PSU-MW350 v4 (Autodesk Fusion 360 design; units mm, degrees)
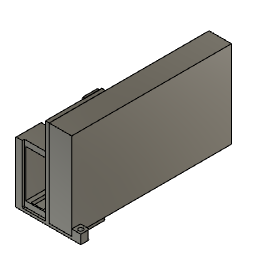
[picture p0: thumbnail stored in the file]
sketch "Sketch1" plane through (0, 0, 0) normal (0, 1, 0) x axis (1, 0, 0)
  line L1 (-34.05, -7.3872) -> (-6.55, -7.3872)
  line L2 (-34.05, -69.3872) -> (-34.05, -7.3872)
  line L3 (-6.55, -69.3872) -> (-34.05, -69.3872)
  line L4 (-6.55, -7.3872) -> (-6.55, -69.3872)
  line L5 (29.5, 0) -> (0, 0)
  line L6 (29.5, -114.5) -> (29.5, 0)
  line L7 (0, -114.5) -> (29.5, -114.5)
  line L8 (0, 0) -> (0, -114.5)
  line L9 (-35.5, -0.1) -> (-5.1, -0.1)
  line L10 (-35.5, -76.6744) -> (-35.5, -0.1)
  line L11 (-5.1, -76.6744) -> (-35.5, -76.6744)
  line L12 (-5.1, -0.1) -> (-5.1, -76.6744)
  line L13 (-5.1, -0.1) -> (-35.5, -76.6744)
  line L14 (-6.55, -69.3872) -> (-34.05, -7.3872)
  line L15 (-44.5, 0) -> (0, 0)
  line L16 (-44.5, -76.7744) -> (-44.5, 0)
  line L17 (-5, -76.7744) -> (-44.5, -76.7744)
  line L18 (-5, -114.5) -> (-5, -76.7744)
  line L19 (0, -114.5) -> (-5, -114.5)
  line L20 (-35.6, 0) -> (-35.6, -76.7744)
  line L21 (-28.3, -2.9315) -> (-28.3, -7.3872)
  line L22 (-12.3, -2.9315) -> (-28.3, -2.9315)
  line L23 (-12.3, -7.3872) -> (-12.3, -2.9315)
  line L24 (-28.3, -73.8428) -> (-28.3, -69.3872)
  line L25 (-12.3, -73.8428) -> (-28.3, -73.8428)
  line L26 (-12.3, -69.3872) -> (-12.3, -73.8428)
  line L27 (-5, 0) -> (-5, -76.7744)
  line L28 (41.5, -8.53) -> (29.5, -8.53)
  line L29 (41.5, 3.47) -> (41.5, -8.53)
  line L30 (-44.5, 3.47) -> (41.5, 3.47)
  line L31 (-44.5, 0) -> (-44.5, 3.47)
  point P1 (0, 0)
  point P14 (-20.3, -38.3872)
  point P15 (-20.3, -38.3872)
  point P16 (0, 0)
  point P21 (0, -114.5)
  point P9 (0, -114.5)
  point P22 (-35.6, -76.7744)
  point P23 (-35.6, 0)
  point P24 (-28.3, -7.3872)
  point P27 (-12.3, -7.3872)
  point P28 (-28.3, -69.3872)
  point P31 (-12.3, -69.3872)
  point P32 (-5, 0)
  point P33 (29.5, -8.53)
  point P17 (-44.5, 0)
  point P37 (-44.5, 0)
  point P6 (0, 0)
  point P7 (29.5, 0)
  point P8 (29.5, -114.5)
  point P4 (-34.05, -69.3872)
  point P5 (-6.55, -69.3872)
  point P3 (-34.05, -7.3872)
  point P11 (-35.5, -0.1)
  point P12 (-35.5, -76.6744)
  point P13 (-5.1, -76.6744)
  point P25 (-28.3, -2.9315)
  point P19 (-5, -76.7744)
  point P34 (41.5, -8.53)
  point P35 (41.5, 3.47)
  horizontal L1
  vertical L2
  horizontal L3
  vertical L4
  horizontal L5
  vertical L6
  horizontal L7
  vertical L8
  coincident P1 L8
  coincident P1 L5
  horizontal L9
  vertical L10
  horizontal L11
  vertical L12
  midpoint L13 P14
  midpoint L14 P15
  coincident P14 P15
  coincident P1 P16
  perpendicular L8 L15
  perpendicular L15 L16
  perpendicular L16 L17
  perpendicular L17 L18
  coincident L8 P21
  perpendicular L8 L19
  coincident P9 P21
  coincident L17 P22
  perpendicular L17 L20
  coincident L15 P23
  coincident L1 P24
  perpendicular L1 L21
  perpendicular L21 L22
  coincident L1 P27
  perpendicular L1 L23
  coincident L3 P28
  perpendicular L3 L24
  perpendicular L24 L25
  coincident L3 P31
  perpendicular L3 L26
  coincident P24 L24
  coincident P27 L26
  equal L21 L24
  perpendicular L15 L27
  coincident L15 P32
  coincident L6 P33
  perpendicular L6 L28
  perpendicular L5 L29
  perpendicular L16 L30
  perpendicular L30 L31
  coincident P17 P37
  dimension "d1" distance P6 P7 = 29.5
  dimension "d2" distance P7 P8 = 114.5
  dimension "d3" distance P4 P5 = 27.5
  dimension "d4" distance P3 P4 = 62
  dimension "d6" distance P11 P12 = 76.5744
  dimension "d7" distance P12 P13 = 30.4
  dimension "d9" distance P1 L9 = 0.1
  dimension "d10" distance P9 L18 = 5
  dimension "d11" distance L11 L17 = 0.1
  dimension "d12" distance L10 L16 = 9
  dimension "d13" distance L10 L20 = 0.1
  dimension "d15" distance P24 P25 = 4.4557
  dimension "d16" distance P14 L24 = 8
  dimension "d17" distance P15 L26 = 8 (= "d16")
  dimension "d18" distance L12 P19 = 0.1
  dimension "d42" distance P33 P34 = 12
  dimension "d43" distance L5 L30 = 3.47
  dimension "d44" distance P34 P35 = 12
extrude "Extrude1" new body sketch "Sketch1" profile of L5 L6 L8 L15 L18 L19 L27 L28 L29 L30 L31 along normal blind 45
extrude "Extrude2" add sketch "Sketch1" profile of L1 L2 L3 L4 L15 L16 L17 L20 L21 L22 L23 L24 L25 L26 L27 along normal blind 33
extrude "Extrude3" cut sketch "Sketch1" profile of L1 L2 L3 L4 L15 L17 L20 L21 L22 L23 L24 L25 L26 L27 along normal blind 3
extrude "Extrude4" sketch "Sketch1" profile of L1 L3 L21 L22 L23 L24 L25 L26 blind 1.5
fillet "Fillet1" radius 1
fillet "Fillet2" radius 3
fillet "Fillet3" radius 1
fillet "Fillet4" radius 1
extrude "Extrude5" new body sketch "Sketch1" profile of L5 L6 L7 L8 along normal blind 210.25 (= "150 mm + 60.25 mm") bodies "PSU"
sketch "Sketch2" plane through (0, 0, 0) normal (-1, 0, 0) x axis (0, -1, 0)
  line L1 (0, 114.5) -> (0, 0)
  line L2 (-210.25, 114.5) -> (0, 114.5)
  line L3 (-210.25, 0) -> (-210.25, 114.5)
  line L4 (0, 0) -> (-210.25, 0)
  line L5 (-180.125, 32.25) -> (-30.125, 32.25)
  line L6 (-180.125, 82.25) -> (-180.125, 32.25)
  line L7 (-30.125, 82.25) -> (-180.125, 82.25)
  line L8 (-30.125, 32.25) -> (-30.125, 82.25)
  line L9 (0, 114.5) -> (-210.25, 0)
  line L10 (-30.125, 32.25) -> (-180.125, 82.25)
  circle C1 centre (-180.125, 82.25) radius 2.25
  circle C2 centre (-180.125, 32.25) radius 2.25
  circle C3 centre (-30.125, 32.25) radius 2.25
  circle C4 centre (-30.125, 82.25) radius 2.25
  point P5 (-210.25, 0)
  point P10 (-210.25, 0)
  point P3 (0, 114.5)
  point P11 (0, 114.5)
  point P12 (-105.125, 57.25)
  point P13 (-105.125, 57.25)
  point P8 (-180.125, 82.25)
  point P14 (-180.125, 82.25)
  point P7 (-180.125, 32.25)
  point P15 (-180.125, 32.25)
  point P6 (-30.125, 32.25)
  point P16 (-30.125, 32.25)
  point P9 (-30.125, 82.25)
  point P17 (-30.125, 82.25)
  horizontal L5
  vertical L6
  horizontal L7
  vertical L8
  coincident P5 P10
  coincident P3 P11
  midpoint L9 P12
  midpoint L10 P13
  coincident P12 P13
  coincident P8 P14
  coincident P7 P15
  coincident P6 P16
  coincident P9 P17
  equal C3 C4
  equal C2 C4
  equal C1 C2
  dimension "d34" distance P6 P9 = 50
  dimension "d35" distance P8 P9 = 150
  dimension "d36" diameter C4 = 4.5
extrude "Extrude6" cut sketch "Sketch2" + "Sketch3" profile of S1:C4 blind 50
sketch "Sketch3" plane through (0, 0, 0) normal (0, 0, -1) x axis (1, 0, 0)
  line L1 (0, 0) -> (29.5, 0)
  line L2 (0, -210.25) -> (0, 0)
  line L3 (29.5, -210.25) -> (0, -210.25)
  line L4 (29.5, 0) -> (29.5, -210.25)
  line L5 (12.5, -30.125) -> (12.5, -180.125)
  circle C1 centre (12.5, -30.125) radius 2.125
  circle C2 centre (12.5, -180.125) radius 2.125
  point P7 (12.5, -180.125)
  point P8 (12.5, -180.125)
  point P6 (12.5, -30.125)
  point P9 (12.5, -30.125)
  point P10 (0, -30.125)
  point P11 (0, -180.125)
  coincident P7 P8
  vertical L5
  coincident P6 P9
  horizontal P6 P10
  horizontal P7 P11
  equal C1 C2
  dimension "d40" diameter C1 = 4.25
  dimension "d41" distance L2 L5 = 12.5
extrude "Extrude7" cut sketch "Sketch3" profile of C1 along normal blind 25
fillet "Fillet5" radius 1
sketch "Sketch4" plane through (0, 0, -3.47) normal (0, 0, -1) x axis (1, 0, 0)
  line L1 (-44.5, 0) -> (41.5, 0)
  line L2 (-44.5, -45) -> (-44.5, 0)
  line L3 (41.5, -45) -> (-44.5, -45)
  line L4 (41.5, 0) -> (41.5, -45)
  line L5 (41.5, -11.54) -> (29.5, -11.54)
  line L6 (-5, -33) -> (-5, -45)
  line L7 (-44.5, -33) -> (-5, -33)
  line L8 (29.5, -210.25) -> (29.5, 0)
  line L9 (-0.1, -186.125) -> (-0.1, -174.125)
  line L10 (18.5, -186.125) -> (-0.1, -186.125)
  line L11 (18.5, -174.125) -> (18.5, -186.125)
  line L12 (-0.1, -174.125) -> (18.5, -174.125)
  line L13 (-12.84, -174.125) -> (-0.1, -174.125)
  line L14 (-12.84, -186.125) -> (-12.84, -174.125)
  line L15 (-0.1, -186.125) -> (-12.84, -186.125)
  line L16 (0, -210.25) -> (0, 0)
  line L17 (-6.47, -180.125) -> (-12.84, -180.125)
  line L18 (-2.64, -186.125) -> (-2.64, -174.125)
  circle C1 centre (12.5, -30.125) radius 2.125
  circle C2 centre (-38.96, -5.54) radius 7.5
  circle C3 centre (-38.96, -5.54) radius 3
  circle C4 centre (35.96, -5.54) radius 3
  circle C5 centre (35.96, -5.54) radius 7.5
  circle C6 centre (-6.47, -180.125) radius 3
  circle C7 centre (-6.47, -180.125) radius 7.5
  circle C8 centre (12.5, -180.125) radius 2.125
  point P9 (-41.96, -5.54)
  point P7 (-38.96, -5.54)
  point P10 (-38.96, -2.54)
  point P8 (-38.96, -5.54)
  point P11 (35.96, -5.54)
  point P15 (38.96, -5.54)
  point P12 (35.96, -5.54)
  point P17 (41.5, -11.54)
  point P18 (-5, -45)
  point P16 (29.5, -11.54)
  point P20 (-44.5, -33)
  point P21 (-44.5, -33)
  point P24 (-5, -45)
  point P25 (12.5, -180.125)
  point P26 (12.5, -180.125)
  point P13 (-6.47, -180.125)
  point P27 (-0.1, -174.125)
  point P31 (-0.1, -174.125)
  point P28 (-0.1, -186.125)
  point P34 (-0.1, -186.125)
  point P37 (-12.84, -180.125)
  point P14 (-6.47, -180.125)
  point P38 (-6.47, -180.125)
  point P39 (-3.47, -180.125)
  point P40 (-9.47, -180.125)
  point P41 (-2.64, -174.125)
  point P42 (-2.64, -186.125)
  point P32 (-12.84, -174.125)
  point P33 (-12.84, -186.125)
  concentric C2 C3
  coincident C3 P9
  horizontal P7 P9
  coincident C3 P10
  vertical P8 P10
  concentric C4 C5
  equal C2 C5
  equal C3 C4
  horizontal P7 P11
  concentric C6 C7
  equal C3 C6
  equal C2 C7
  coincident C4 P15
  horizontal P12 P15
  coincident L4 P17
  perpendicular L4 L5
  coincident L3 P18
  perpendicular L3 L6
  perpendicular L6 L7
  coincident P16 L8
  coincident P20 P21
  coincident P18 P24
  coincident P25 P26
  horizontal P13 P26
  vertical L9
  perpendicular L9 L10
  perpendicular L10 L11
  perpendicular L9 L12
  coincident P27 P31
  perpendicular L9 L13
  perpendicular L12 L14
  perpendicular L9 L15
  coincident P28 P34
  midpoint L14 P37
  perpendicular L14 L17
  coincident P14 P38
  coincident C6 P39
  coincident C6 P40
  coincident L17 P40
  horizontal P13 P39
  coincident L13 P41
  coincident L15 P42
  perpendicular L15 L18
  dimension "d48" diameter C3 = 6
  dimension "d49" diameter C2 = 15
  dimension "d50" = 6
  dimension "d52" distance L2 P9 = 2.54
  dimension "d53" distance L1 P10 = 2.54 (= "d52")
  dimension "d55" distance L4 P15 = 2.54
  dimension "d56" distance P11 L5 = 6
  dimension "d60" diameter C8 = 4.25
  dimension "d61" distance L9 L16 = 0.1
  dimension "d62" distance P26 L11 = 6
  dimension "d63" distance P32 P33 = 12
  dimension "d64" distance P27 P39 = 3.37
  dimension "d65" distance L14 P40 = 3.37 (= "d64")
  dimension "d66" distance P31 L18 = 2.54
extrude "Extrude9" new body sketch "Sketch4" profile of C6 C7 C8 L9 L10 L11 L12 L13 L14 L15 L16 L18 to an object bodies "Step"
extrude "Extrude8" cut sketch "Sketch4" profile of L2 L3 L4 C3 C4 C5 L5 L6 L7 L8 against normal blind 12
extrude "Extrude10" add sketch "Sketch4" profile of C6 C7 L9 L13 L14 L15 L18 against normal blind 12
extrude "Extrude11" add sketch "Sketch4" profile of C7 L9 L13 L15 L18 against normal blind 60
extrude "Extrude12" cut sketch "Sketch2" profile of C2 along normal blind 25
sketch "Sketch5" plane through (-5, 0, 0) normal (-1, 0, 0) x axis (0, -1, 0)
  line L1 (-33, 79.7744) -> (-33, -3.47)
  line L2 (-3, 79.7744) -> (-33, 79.7744)
  line L3 (-3, 1) -> (-3, 79.7744)
  line L4 (0, 1) -> (-3, 1)
  line L5 (0, 114.5) -> (0, 1)
  line L6 (-45, 114.5) -> (0, 114.5)
  line L7 (-45, -3.47) -> (-45, 114.5)
  line L8 (-33, -3.47) -> (-45, -3.47)
  line L9 (-53, 68) -> (-73, 68)
  line L10 (-53, 43) -> (-53, 68)
  line L11 (-73, 43) -> (-53, 43)
  line L12 (-73, 68) -> (-73, 43)
  line L13 (-73, 88) -> (-73, 68)
  line L14 (-53, 88) -> (-73, 88)
  line L15 (-53, 68) -> (-53, 88)
  line L16 (-73, 108) -> (-73, 88)
  line L17 (-53, 108) -> (-73, 108)
  line L18 (-53, 88) -> (-53, 108)
  line L19 (-73, 18) -> (-73, 43)
  line L20 (-53, 18) -> (-73, 18)
  line L21 (-53, 43) -> (-53, 18)
  line L22 (-73, 3) -> (-73, 18)
  line L23 (-53, 3) -> (-73, 3)
  line L24 (-53, 18) -> (-53, 3)
  line L25 (-53, 28) -> (-73, 28)
  line L26 (-76, 114.5) -> (-45, 114.5)
  line L27 (-76, -3.47) -> (-76, 114.5)
  line L28 (-45, -3.47) -> (-76, -3.47)
  line L29 (-52, 113) -> (-74, 113)
  line L30 (-52, -2) -> (-52, 113)
  line L31
  line L32 (-74, 113) -> (-74, -2)
  circle C1 centre (-30.125, 82.25) radius 2.25
  circle C2 centre (-63, 108) radius 2.7
  circle C3 centre (-63, 88) radius 2.7
  circle C4 centre (-63, 68) radius 2.7
  circle C5 centre (-63, 43) radius 2.7
  circle C6 centre (-63, 18) radius 2.7
  circle C7 centre (-63, 3) radius 2.7
  circle C8 centre (-69.5, 108) radius 2.7
  circle C9 centre (-69.5, 88) radius 2.7
  circle C10 centre (-69.5, 68) radius 2.7
  circle C11 centre (-69.5, 43) radius 2.7
  circle C12 centre (-69.5, 18) radius 2.7
  circle C13 centre (-69.5, 3) radius 2.7
  circle C14 centre (-56.5, 3) radius 2.7
  circle C15 centre (-56.5, 88) radius 2.7
  circle C16 centre (-56.5, 18) radius 2.7
  circle C17 centre (-56.5, 43) radius 2.7
  circle C18 centre (-56.5, 68) radius 2.7
  circle C19 centre (-56.5, 108) radius 2.7
  point P12 (-53, 68)
  point P17 (-53, 68)
  point P16 (-53, 88)
  point P20 (-53, 88)
  point P13 (-53, 43)
  point P23 (-53, 43)
  point P22 (-53, 18)
  point P26 (-53, 18)
  point P27 (-73, 28)
  point P28 (-53, 28)
  point P29 (-63, 108)
  point P30 (-63, 88)
  point P31 (-63, 68)
  point P32 (-63, 43)
  point P33 (-63, 18)
  point P34 (-63, 3)
  point P38 (-69.5, 43)
  point P39 (-69.5, 18)
  point P36 (-69.5, 88)
  point P37 (-69.5, 68)
  point P40 (-69.5, 3)
  point P35 (-69.5, 108)
  point P45 (-56.5, 43)
  point P46 (-56.5, 18)
  point P42 (-56.5, 88)
  point P44 (-56.5, 68)
  point P43 (-56.5, 3)
  point P41 (-56.5, 108)
  point P9 (-45, 114.5)
  point P47 (-45, 114.5)
  point P50 (-45, -3.47)
  point P51 (-45, -3.47)
  point P14 (-73, 43)
  point P19 (-53, 108)
  point P25 (-53, 3)
  point P18 (-73, 108)
  horizontal L9
  vertical L10
  horizontal L11
  vertical L12
  perpendicular L9 L13
  perpendicular L13 L14
  perpendicular L14 L15
  coincident P12 P17
  perpendicular L14 L16
  perpendicular L16 L17
  perpendicular L17 L18
  coincident P16 P20
  perpendicular L11 L19
  perpendicular L19 L20
  perpendicular L20 L21
  coincident P13 P23
  perpendicular L20 L22
  perpendicular L22 L23
  perpendicular L20 L24
  coincident P22 P26
  coincident L19 P27
  coincident L21 P28
  perpendicular L21 L25
  midpoint L17 P29
  midpoint L14 P30
  midpoint L9 P31
  midpoint L11 P32
  midpoint L20 P33
  midpoint L23 P34
  equal C5 C7
  equal C5 C6
  equal C2 C6
  equal C2 C3
  equal C3 C4
  vertical P38 P39
  vertical P36 P38
  vertical P36 P37
  vertical P37 P40
  vertical P35 P40
  equal C10 C12
  equal C8 C12
  equal C8 C11
  equal C11 C13
  equal C9 C13
  equal C2 C8
  vertical P45 P46
  vertical P42 P45
  vertical P42 P44
  vertical P43 P44
  vertical P41 P43
  equal C16 C18
  equal C16 C19
  equal C17 C19
  equal C14 C17
  equal C14 C15
  horizontal P35 P41
  horizontal P36 P42
  horizontal P37 P44
  horizontal P38 P45
  horizontal P39 P46
  horizontal P40 P43
  coincident L17 P35
  equal C2 C19
  coincident L14 P36
  coincident L9 P37
  coincident L11 P38
  coincident L20 P39
  coincident L23 P40
  coincident P9 P47
  perpendicular L7 L26
  perpendicular L6 L27
  coincident L7 P50
  perpendicular L7 L28
  coincident L28 P51
  horizontal L29
  vertical L30
  horizontal L31
  vertical L32
  dimension "d75" distance P13 P14 = 20
  dimension "d76" distance P12 P13 = 25
  dimension "d77" distance P16 P17 = 20
  dimension "d78" distance P19 P20 = 20
  dimension "d79" distance P22 P23 = 25
  dimension "d80" distance P25 P26 = 15
  dimension "d81" distance P13 L25 = 15
  dimension "d82" diameter C2 = 5.4
  dimension "d83" distance P29 P35 = 6.5
  dimension "d84" distance P29 P41 = 6.5
  dimension "d85" distance L7 P19 = 8
  dimension "d86" distance P19 L26 = 6.5
  dimension "d87" distance P18 L27 = 3
  dimension "d101" distance P43 L31 = 5
  dimension "d102" distance P25 L30 = 1
  dimension "d103" distance L22 L32 = 1
  dimension "d104" distance P41 L29 = 5
  dimension "d112" distance L28 L31 = 1.97
  dimension "d113" = 1
extrude "Extrude13" new body sketch "Sketch5" profile of L7 C2 C3 C4 C5 C6 C7 C8 C9 C10 C11 C12 C13 C14 C15 C16 C17 C18 C19 L26 L27 L28 to an object
extrude "Extrude14" add sketch "Sketch5" profile of C2 C3 C4 C5 C6 C7 C8 C9 C10 C11 C12 C13 C14 C15 C16 C17 C18 C19 L29 L30 L31 L32 along normal blind 4
extrude "Extrude15" cut sketch "Sketch5" profile of C2 C3 C4 C5 C6 C7 C8 C9 C10 C11 C12 C13 C14 C15 C16 C17 C18 C19 against normal blind 3
combine "Combine1"
chamfer "Chamfer1" distance 4
fillet "Fillet16" radius 2
fillet "Fillet17" radius 1
offset_faces "OffsetFaces1" distance -0.1
offset_faces "OffsetFaces2" distance -0.1
fillet "Fillet7" radius 1
fillet "Fillet8" radius 2
fillet "Fillet9" radius 3
fillet "Fillet10" radius 2
fillet "Fillet11" radius 1
fillet "Fillet12" radius 2
fillet "Fillet13" radius 2
fillet "Fillet14" radius 2
fillet "Fillet15" radius 2
named bodies: "Front", "PSU", "Step"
